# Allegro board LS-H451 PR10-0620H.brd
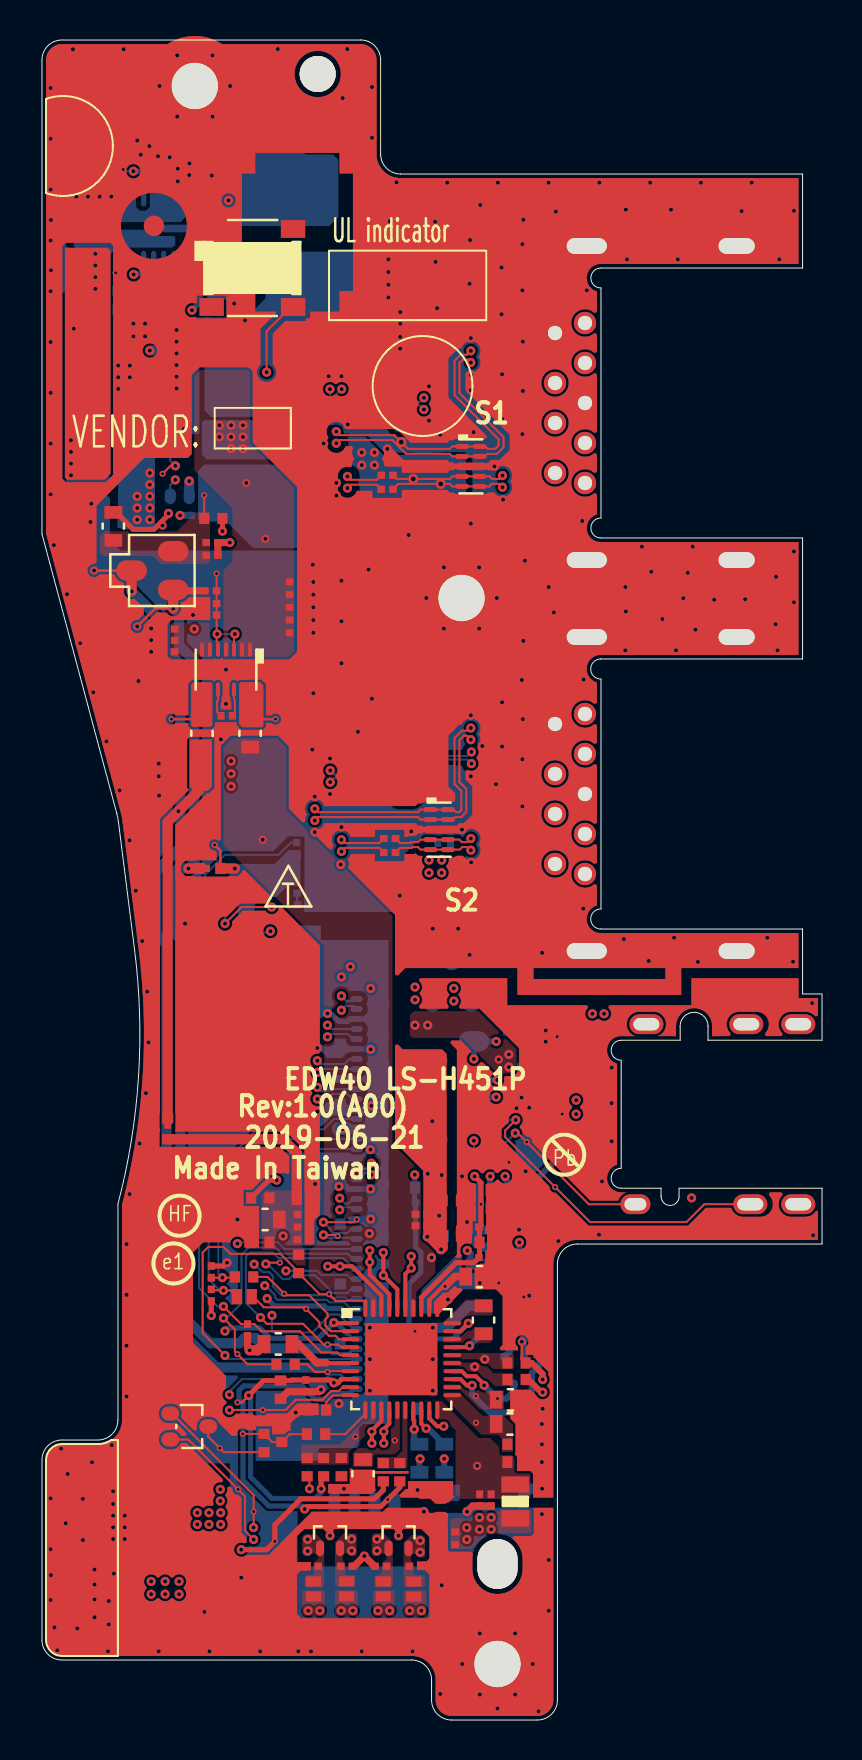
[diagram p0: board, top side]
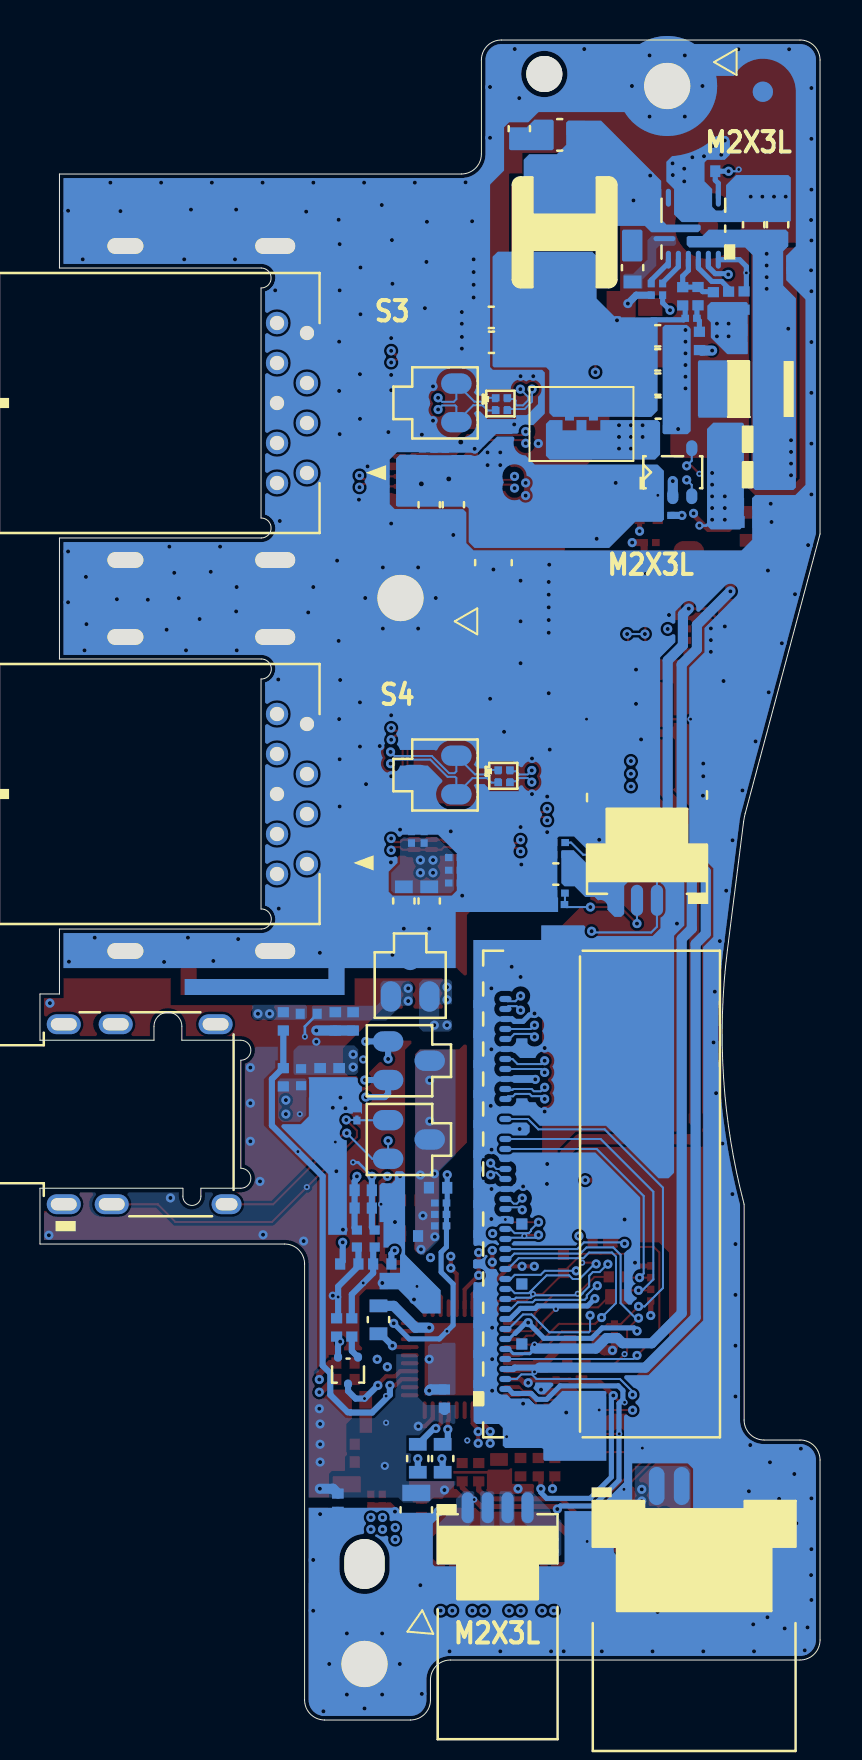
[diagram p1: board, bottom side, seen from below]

Outline 39.05 x 84 mm; copper layers: TOP, GND1, IN1, IN2, GND2, BOTTOM. Coordinates in mm from the lower left corner of the outline.
Outline path: 0,83 arc(0.29,83.71) 1,84 15.95,84 arc(16.66,83.71) 16.95,83 16.95,78.3 arc(17.24,77.59) 17.95,77.3 38.07,77.3 38.07,72.6 27.97,72.6 arc(27.47,72.1) 27.98,71.6 27.98,60.1 arc(27.47,59.61) 27.97,59.1 38.07,59.1 38.07,53.05 27.97,53.05 arc(27.47,52.55) 27.98,52.05 27.98,40.55 arc(27.47,40.06) 27.97,39.55 38.07,39.55 38.07,36.3 39.05,36.3 39.05,33.99 33.34,33.99 33.34,34.69 arc(32.64,35.39) 31.94,34.69 31.94,33.99 28.99,33.99 arc(28.49,33.49) 28.99,32.99 28.99,27.59 arc(28.49,27.09) 28.99,26.59 30.99,26.59 30.99,26.19 arc(31.44,25.74) 31.89,26.19 31.89,26.59 39.05,26.59 39.05,23.8 26.8,23.8 arc(26.09,23.51) 25.8,22.8 25.8,1 arc(25.51,0.29) 24.8,0 20.5,0 arc(19.79,0.29) 19.5,1 19.5,2 arc(19.21,2.71) 18.5,3 1,3 arc(0.29,3.29) 0,4 0,13 arc(0.29,13.71) 1,14 2.8,14 arc(3.51,14.29) 3.8,15 3.8,25.79 arc(4.83,32.1) 4.64,38.5 3.83,44.92 arc(3.79,45.12) 3.75,45.32 0,59.3 0,83

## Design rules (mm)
net group DMIC: nets DMIC_DATA DMIC_DATA_CODEC
net group USB3_CRX_DTX_3: nets USB3_CRX_DTX_N3 USB3_CRX_DTX_P3
net group USB3_CRX_DTX_4: nets USB3_CRX_DTX_N4 USB3_CRX_DTX_P4
net group USB3_CTX_C_DRX_3: nets USB3_CTX_C_DRX_N3 USB3_CTX_C_DRX_P3
net group USB3_CTX_C_DRX_4: nets USB3_CTX_C_DRX_N4 USB3_CTX_C_DRX_P4
net group USB3_CTX_DRX_3: nets USB3_CTX_DRX_N3 USB3_CTX_DRX_P3
net group USB3_CTX_DRX_4: nets USB3_CTX_DRX_N4 USB3_CTX_DRX_P4
net group USB20_1_R: nets USB20_N1_R USB20_P1_R
net group USB20_1_R1: nets USB20_N1_R1 USB20_P1_R1
net group USB20_2_R: nets USB20_N2_R USB20_P2_R
net group USB20_2_R1: nets USB20_N2_R1 USB20_P2_R1
net group 10.6: nets HDA_BIT_CLK_R
net group 15: nets AUD_HP1_JACK_L1 AUD_HP1_JACK_R1 DMIC_CLK DMIC_CLK_CODEC HPOUT_L HPOUT_R LINE1-L_C LINE1-L_R LINE1_L LINE1_R
net group HDA: nets HDA_SDIN0 HDA_SDIN0_R HDA_SDOUT_R HDA_SYNC_R
net group UA7: nets +LINE1_VREFO_L +MIC2-VREFO LDO2_CAP
nets with their own width: min track width 0.254; nets +1.8V_CPVDD +1.8VS_AUDIO +3V_DVDD +3VALW +5V_AVDD +5VS_FAN +RTC_CELL
nets with their own width: min track width 0.305; nets AUD_HP1_JACK_L AUD_HP1_JACK_R CBN CBP CPVEE
nets with their own width: min track width 0.381; nets BST_5VB LDO1_CAP LDO3_CAP MIC_CAP
nets with their own width: min track width 0.508; nets +1.8V_PRIM +3VS_AUDIO +3VS_AUDIO_R +5VS AGND AUD_AGND GND
nets with their own width: min track width 1.016; nets RING2 RING2_R SLEEVE SLEEVE_R SPK_-OUT-L+ SPK_-OUT-L- SPK_-OUT-R+ SPK_-OUT-R- SPK_L+ SPK_L- SPK_R+ SPK_R-
nets with their own width: min track width 2.032; nets +USB3_VCC
nets with their own width: min track width 3.048; nets +5VS_AUDIO +5VS_AUDIO_R
nets with their own width: min track width 3.302; nets +5VALW
nets with their own width: min track width 3.556; nets +5VALWBP
nets with their own width: min track width 4.064; nets B+

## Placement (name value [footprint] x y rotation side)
C27  22U_0603_6.3V6M  [C_0603]  12.51 42.3 0 bottom
C84  100P_0201_25V8J  [C_0201]  12.75 43.26 0 bottom
C123  82P_0201_25V8J  [C_0201]  12.77 41.34 0 bottom
C124  82P_0201_25V8J  [C_0201]  12.75 43.87 0 bottom
CA14  0.1U_0402_16V7K  [C_0402]  13.26 14.29 0 top
CA18  1U_0603_16V7  [C_0603]  22.1 19.31 90 bottom
CA19  10U_0402_10V6M  [C_0402]  23.3 12.9 0 top
CA20  10U_0603_6.3V6M  [C_0603]  24.13 14.8 180 top
CA24  0.1U_0201_10V6K  [C_0201]  21.87 23.12 0 top
CA29  10U_0402_10V6M  [C_0402]  21.9 23.88 0 top
CA32  10U_0603_6.3V6M  [C_0603]  11.12 18.8 0 top
CA33  0.1U_0201_10V6K  [C_0201]  13.21 17 270 top
CA36  680P_0402_50V7K  [C_0402]  25.02 32.59 270 bottom
CA37  680P_0402_50V7K  [C_0402]  24.26 35.39 270 bottom
CA39  10U_0402_6.3V6M  [C_0402]  11.94 16.97 270 top
CA44  1000P_0201_25V7K  [C_0201]  17.25 7.69 180 top
CA45  1000P_0201_25V7K  [C_0201]  18.38 7.69 0 top
CA49  1000P_0201_25V7K  [C_0201]  14.95 7.69 0 top
CA50  1000P_0201_25V7K  [C_0201]  13.82 7.69 180 top
CA51  10U_0603_6.3V6M  [C_0603]  22.61 22.17 180 top
CA81  0.1U_0402_25V6  [C_0402]  21.03 24.2 180 bottom
CA82  0.1U_0402_25V6  [C_0402]  20.97 24.2 180 top
CA83  0.1U_0402_25V6  [C_0402]  24.13 11.32 270 bottom
CA144  3300P_0201_25V7K  [C_0201]  9.53 50.21 270 top
CA145  1000P_0201_25V7K  [C_0201]  8.96 50.21 270 top
CA146  1U_0201_6.3V6M  [C_0201]  6.65 53.98 180 top
CA147  0.1U_0201_10V6K  [C_0201]  7.6 47.19 180 top
CA148  0.1U_0201_10V6K  [C_0201]  18.7 24.71 0 top
CA150  0.1U_0201_10V6K  [C_0201]  12.79 24.64 0 top
CA151  10U_0402_6.3V6M  [C_0402]  11.38 23.88 180 top
CA152  1U_0201_6.3V6M  [C_0201]  12.4 55.63 0 top
CA153  0.1U_0201_10V6K  [C_0201]  8.22 58.87 0 top
CA161  680P_0402_50V7K  [C_0402]  22.43 26.49 180 bottom
CA162  680P_0402_50V7K  [C_0402]  23.3 26.49 0 bottom
CA163  680P_0402_50V7K  [C_0402]  23.37 35.39 270 bottom
CA164  680P_0402_50V7K  [C_0402]  24.07 32.59 270 bottom
CA165  10U_0603_10V6M  [C_0603]  20.13 13.79 270 bottom
CA166  10U_0603_10V6M  [C_0603]  18.89 13.79 270 bottom
CA300  68P_0201_25V8  [C_0201]  19.28 25.28 180 top
CA301  68P_0201_25V8  [C_0201]  7.01 47.82 0 top
CA302  68P_0201_25V8  [C_0201]  6.06 53.41 0 top
CA305  0.1U_0201_10V6K  [C_0201]  6.65 54.55 180 top
CA306  68P_0201_25V8  [C_0201]  12.98 55 180 top
CA307  0.1U_0201_10V6K  [C_0201]  12.4 54.36 0 top
CA309  68P_0201_25V8  [C_0201]  22.46 24.64 180 top
CA313  100P_0201_25V8J  [C_0201]  8.22 58.24 0 top
CA379  68P_0201_50V8J  [C_0201]  12.79 25.28 0 top
CA380  10U_0603_6.3V6M  [C_0603]  16.07 13.02 270 top
CA382  .1U_0402_16V7K  [C_0402]  14.99 13.1 270 top
CA383  10U_0603_6.3V6M  [C_0603]  11.88 25.03 180 top
CA384  10P_0201_50V8J  [C_0201]  12.79 24.01 0 top
CA386  2.2U_0603_6.3V6K  [C_0603]  22.1 20.71 270 top
CA387  68P_0201_50V8J  [C_0201]  18.7 25.85 0 bottom
CA390  10P_0201_50V8J  [C_0201]  21.91 11.28 270 top
CA393  10P_0201_50V8J  [C_0201]  20.68 9.4 180 top
CA394  2.2U_0603_6.3V6K  [C_0603]  22.74 16.01 0 top
CA395  10P_0201_50V8J  [C_0201]  18.7 25.28 0 bottom
CA396  .1U_0402_16V7K  [C_0402]  12.75 26.04 0 top
CA399  68P_0201_50V8J  [C_0201]  22.48 11.28 270 top
CA401  68P_0201_50V8J  [C_0201]  20.68 8.77 180 top
CA429  10U_0402_10V6M  [C_0402]  18.66 26.61 0 bottom
CA430  0.1U_0201_10V6K  [C_0201]  18.7 24.71 0 bottom
CA555  47P_0201_25V8J  [C_0201]  10.29 19.21 90 top
CA568  82P_0201_25V8J  [C_0201]  8.47 22.12 90 top
CA569  82P_0201_25V8J  [C_0201]  8.47 21.53 270 top
CA999  0.1U_0201_10V6K  [C_0201]  8.74 55.25 180 top
CA1000  0.1U_0402_25V6  [C_0402]  20.97 25.98 180 top
CE99  0.01U_0201_16V7  [C_0201]  12.79 40.77 0 bottom
CI140  0.1U_0201_10V6K  [C_0201]  17.11 43.38 0 top
CI141  0.1U_0201_10V6K  [C_0201]  17.11 44.08 0 top
CI142  0.1U_0201_10V6K  [C_0201]  16.98 61.54 0 top
CI143  0.1U_0201_10V6K  [C_0201]  16.98 62.24 0 top
CU3  1U_0201_6.3V6M  [C_0201]  19.9 62.99 90 bottom
CU4  1U_0201_6.3V6M  [C_0201]  20.48 60.92 270 bottom
CU5  22U_0603_6.3V6M  [C_0603]  18.36 61.47 270 bottom
CU6  22U_0603_6.3V6M  [C_0603]  19.56 61.47 270 bottom
CU7  100U_1206_6.3V6M  [C_1206]  16.35 59.19 270 bottom
CU8  100P_0201_25V8J  [C_0201]  18.75 63.56 270 bottom
CU9  0.1U_0201_10V6K  [C_0201]  19.32 62.97 90 bottom
CU10  12P_0201_25V8J  [C_0201]  21.05 60.92 270 bottom
CU13  1U_0201_6.3V6M  [C_0201]  8.26 64.55 180 bottom
CU16  100P_0201_25V8J  [C_0201]  12.98 56.27 180 top
CU17  0.1U_0201_10V6K  [C_0201]  12.4 56.9 0 top
CU18  0.1U_0201_10V6K  [C_0201]  8.04 60.23 180 bottom
CU19  22U_0603_6.3V6M  [C_0603]  19.56 41.66 270 bottom
CU20  22U_0603_6.3V6M  [C_0603]  20.83 41.66 270 bottom
CU21  1U_0201_6.3V6M  [C_0201]  19.82 43.85 90 bottom
CU23  1U_0201_6.3V6M  [C_0201]  20.45 43.85 90 bottom
CU24  100P_0201_25V8J  [C_0201]  18 41.85 0 bottom
CU25  0.1U_0201_10V6K  [C_0201]  18.58 42.49 180 bottom
CU26  12P_0201_25V8J  [C_0201]  18.58 43.12 180 bottom
DA8  CEST523NC5VB 3P C/A SOT-523  [L03ESDL5V0CG3-2_SOT-523-3]  17.85 9.98 0 top
DA9  CEST523NC5VB 3P C/A SOT-523  [L03ESDL5V0CG3-2_SOT-523-3]  14.42 9.98 0 top
DA14  AZ5125-02S.R7G_SOT23-3  [AZ5125-02SPR7G_SOT23-3]  19.54 29.03 90 bottom
DA15  AZ5125-02S.R7G_SOT23-3  [AZ5125-02SPR7G_SOT23-3]  19.54 32.96 90 bottom
DA16  AZ5123-02S.R7G_SOT23-3  [AZ5123-02SPR7G_SOT23-3]  20.51 38.26 0 bottom
DA18  BAT54ATB_SOT-523-3  [BAT54ATB_SOT523-3]  23.63 16.79 180 bottom
DA19  -  [BAT54CW_SOT323-3]  8.32 14.67 270 top
DI1  -  [CEST23LC5VB_SOT23-3]  20.29 65.86 270 bottom
DI2  -  [CEST23LC5VB_SOT23-3]  20.29 47.25 270 bottom
EU1  -  [AZ1045-04F_DFN2510P10E-10-9]  21.03 63.68 270 top
EU8  -  [AZ1045-04F_DFN2510P10E-10-9]  19.44 45.52 270 top
FD1  FIDUCAL  [FIDUCIAL_C40M80]  5.6 74.71 0 top
FD2  FIDUCIAL  [FIDUCIAL_C40M80]  2.86 81.41 180 bottom
H1  HOLEA  [H_2P3-G]  21 56.1 0 top
H2  HOLEA  [H_2P3-G]  22.8 2.8 0 top
H3  HOLEA  [H_1P8N]  13.8 82.3 0 top
H20  HOLEA  [H_2P5X2P0N]  22.8 7.8 90 top
H21  HOLEA  [H_2P3-G]  7.65 81.7 0 top
JFAN1  ACES_50224-00401-001  [ACES_50224-00401-001_4P]  7.16 40.98 0 bottom
JHP1  YUQIU_PJ036-F06M1BE-A  [YUQIU_PJ036-F06M1BE-A_6P-T]  37.85 25.79 90 bottom
JIO1  I-PEX_20849-040E-01  [I-PEX_20849-040E-01_40P-T]  15.75 16.55 90 bottom
JIO2  ACES_50279-0040C-P01  [ACES_50279-0040C-P01_4P]  8.17 11.7 180 bottom
JSPK1  ACES_50224-00401-001  [ACES_50224-00401-001_4P]  17.64 10.62 180 bottom
JUSB1  LOTES_AUSB0014-P003A  [LOTES_AUSB0014-P003A_9P]  25.68 62.35 270 bottom
JUSB2  LOTES_AUSB0014-P003A  [LOTES_AUSB0014-P003A_9P]  25.68 42.8 270 bottom
L7  BLM15PX471SN1D_2P  [MURAT_BLM15PX471SN1D_2P]  9.75 21.16 0 top
LA1  HCB2012KF-600T30  [TAI-T_HCB2012KF-121T50_2P]  23.69 11.78 270 top
LA5  BLM15PX181SN1D_2P  [MURAT_BLM15PX181SN1D_2P]  13.59 6.18 90 top
LA6  BLM15PX181SN1D_2P  [MURAT_BLM15PX181SN1D_2P]  15.24 6.18 90 top
LA7  BLM15PX181SN1D_2P  [MURAT_BLM15PX181SN1D_2P]  17.09 6.18 90 top
LA8  BLM15PX181SN1D_2P  [MURAT_BLM15PX181SN1D_2P]  18.61 6.17 90 top
LA27  BLM15PX330SN1D_2P  [MURAT_BLM15PX330SN1D_2P]  26.02 35.31 180 bottom
LA28  BLM15PD800SN1D_2P  [MURAT_BLM15PD800SN1D_2P]  22.29 23.65 90 bottom
LA29  BLM15PX330SN1D_2P  [MURAT_BLM15PX330SN1D_2P]  25.98 31.71 90 bottom
LA30  BLM15PD800SN1D_2P  [MURAT_BLM15PD800SN1D_2P]  23.18 23.65 90 bottom
LU1  DLM0NSN900HY2D_4P  [MURAT_DLM0NSN900HY2D_4P-NPM]  16.26 66.05 180 bottom
LU2  DLM0NSN900HY2D_4P  [MURAT_DLM0NSN900HY2D_4P-NPM]  16.12 47.44 180 bottom
NOREF  -  []  1.28 63.7 0 top
NOREF#2  -  []  21 56.1 0 top
NOREF#3  -  []  22.8 2.8 0 top
NOREF#4  -  []  -1.33 -39.24 0 top
NOREF#5  -  []  6.32 72.2 0 top
NOREF#6  -  []  11.19 40.68 0 top
NOREF#7  -  []  5.69 32.96 0 top
NOREF#8  -  []  7.65 81.7 0 top
NOREF#9  -  []  22.8 2.8 0 top
NOREF#10  -  []  -72.55 45.68 0 top
PC517  33U_B3_16VM_R45M  [C_B3]  2.69 66.55 0 bottom
PC518  0.1U_0402_25V6  [C_0402]  2.97 69.51 0 bottom
PC519  2200P_0402_50V7K  [C_0402]  2.98 68.61 0 bottom
PC520  10U_0603_25V6M  [C_0603]  2.12 74.05 90 bottom
PC521  10U_0603_25V6M  [C_0603]  3.32 74.05 90 bottom
PC522  22U_0603_6.3V6M  [C_0603]  8.83 69.21 180 bottom
PC523  22U_0603_6.3V6M  [C_0603]  8.83 68.01 180 bottom
PC524  22U_0603_6.3V6M  [C_0603]  8.83 66.79 180 bottom
PC525  22U_0603_6.3V6M  [C_0603]  15.74 70.13 0 bottom
PC526  22U_0603_6.3V6M  [C_0603]  15.74 68.89 0 bottom
PC527  22U_0603_6.3V6M  [C_0603]  8.82 65.6 180 bottom
PC528  2.2U_0402_6.3V6M  [C_0402]  5.24 77.44 0 bottom
PC529  0.22U_0402_16V7K  [C_0402]  9.31 74.24 90 bottom
PC530  220P_0201_25V7K  [C_0201]  6.16 70.08 0 bottom
PC531  680P_0603_50V7K  [C_0603]  15.05 78.86 90 bottom
PC535  1000P_0402_25V8J  [C_0402]  4.05 60.81 180 bottom
PC536  1U_0402_25V6K  [C_0402]  4.02 59.9 180 bottom
PC541  100P_0201_25V8J  [C_0201]  16.16 72.4 0 bottom
PC542  100P_0201_25V8J  [C_0201]  16.16 71.76 0 bottom
PC543  2200P_0201_16V7K  [C_0201]  16.16 71.13 0 bottom
PC544  0.1U_0201_6.3V6K  [C_0201]  16.16 73.03 0 bottom
PC545  100P_0201_25V8J  [C_0201]  2.07 73.06 180 bottom
PC546  100P_0201_25V8J  [C_0201]  2.07 72.48 180 bottom
PJP502  PAD-OPEN 4x4m  [JUMP_43X118]  11.94 65.35 270 bottom
PL502  1.5UH_MMD-05AHN1R5M-M1L_6.2A_20%  [MAG_MMD-05AHN1R5M-M1L_2P]  12.78 76.56 270 bottom
PL513  -  [5A_Z80_0805_2P]  4.47 62.26 180 bottom
PL514  -  [5A_Z80_0805_2P]  4.47 64.04 180 bottom
PR511  150K_0201_5%  [R_0201]  7.88 71.82 270 bottom
PR512  0_0402_5%  [R_0402]  3.8 70.52 90 bottom
PR513  0_0201_5%  [R_0201]  8.45 71.24 90 bottom
PR514  0_0603_5%  [R_0603]  9.38 71.91 90 bottom
PR515  0_0402_5%  [R_0402]  4.58 71.42 270 bottom
PR516  274K_0402_1%  [R_0402]  6.04 68.5 90 bottom
PR517  499_0402_1%  [R_0402]  6.11 70.74 90 bottom
PR518  19.1K_0402_1%  [R_0402]  6.87 70.73 90 bottom
PR519  10K_0402_1%  [R_0402]  5.34 71.39 270 bottom
PR520  4.7_0805_5%  [R_0805]  12.18 79.26 0 bottom
PU502  -  [NB502GQ-Z_QFN16_3X3]  5.49 74.07 0 bottom
QA1  -  [LN2306LT1G_SOT23-3]  4.49 57.47 270 top
RA9  1K_0402_5%  [R_0402]  11.12 13.39 90 top
RA10  100K_0402_5%  [R_0402]  24.21 13.79 180 top
RA17  33_0402_5%  [R_0402]  11.74 17.79 0 top
RA22  0_0402_5%  [R_0402]  19.94 11.07 270 top
RA23  0_0402_5%  [R_0402]  18.8 15.61 90 bottom
RA25  0_0805_5%  [R_0805]  20.21 11.36 270 bottom
RA29  0_0402_5%  [R0402_0OHM]  6.29 29.95 270 top
RA32  1K_0402_5%  [R_0402]  24.21 17.85 180 top
RA33  4.7K_0402_5%  [R_0402]  24.2 19.17 90 bottom
RA36  0_0402_5%  [R_0402]  10.47 26.1 0 top
RA112  0.01_0603_1%  [R_0603]  3.57 58.98 90 top
RA115  0.01_0603_1%  [R_0603]  8 50.04 270 top
RA116  0.01_0603_1%  [R_0603]  10.42 50.04 270 top
RA122  10K_0201_5%  [R_0201]  8.16 56.46 0 top
RA133  10_0402_1%  [R_0402]  21.45 22.8 0 bottom
RA134  10_0402_1%  [R_0402]  24.02 22.8 180 bottom
RA168  0_0201_5%  [R0201_0OHM]  23.18 30 90 bottom
RA169  2.2K_0402_5%  [R_0402]  26.86 34.47 90 bottom
RA170  10K_0402_5%  [R_0402]  22.43 25.6 180 bottom
RA171  10K_0402_5%  [R_0402]  23.3 25.6 0 bottom
RA172  2.2K_0402_5%  [R_0402]  26.86 32.59 270 bottom
RA200  4.7K_0402_5%  [R_0402]  23.44 19.17 90 bottom
RA202  1K_0402_5%  [R_0402]  24.21 17.02 180 top
RA206  100K_0402_5%  [R_0402]  12.84 23.26 270 top
RA207  200K_0402_1%  [R_0402]  13.28 12.19 90 top
RA209  0_0402_5%  [R_0402]  13.31 15.5 0 top
RA213  0_0402_5%  [R_0402]  17.09 12.85 270 top
RA217  100K_0402_5%  [R_0402]  14.1 13.1 270 top
RA222  33_0402_5%  [R_0402]  9.66 22.15 0 top
RA225  0_0402_5%  [R_0402]  8.12 60.08 0 top
RA227  0_0402_5%  [R_0402]  17.91 12.85 270 top
RA511  20K_0201_5%  [R_0201]  8.74 55.82 180 top
RF10  0_0402_5%  [R0402_0OHM]  8.02 42.58 0 top
RU1  0_0201_5%  [R_0201]  15.65 65.47 0 bottom
RU2  0_0201_5%  [R_0201]  15.65 66.11 0 bottom
RU3  0_0201_5%  [R_0201]  15.52 47.5 0 bottom
RU4  0_0201_5%  [R_0201]  15.52 46.87 0 bottom
RV30  10K_0402_5%  [R_0402]  12.01 13.9 90 top
SW3  SKRBACE010_4P  [SW_SKRBACE010_4P]  8.49 74.55 0 top
UA2  AOZ1331DI_DFN_14  [EM5209VF_DFN14_3X2]  10.41 53.52 180 top
UA7  -  [ALC3204-CG_MQFN40_5X5]  15.44 19.84 0 top
UU1  -  [SY6288D20AAC_SOT23-5]  8.32 61.19 180 bottom

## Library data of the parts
C27 CA18 CA20 CA32 CA51 CA165 CA166 CA380 CA383 CA386 CA394 CU5 CU6 CU19 CU20 PC520-PC527 PC531 = C_0603
C84 C123 C124 CA24 CA33 CA44 CA45 CA49 CA50 CA144-CA148 CA150 CA152 CA153 CA300-CA302 CA305-CA307 CA309 CA313 CA379 CA384 CA387 CA390 CA393 CA395 CA399 CA401 CA430 CA555 CA568 CA569 CA999 CE99 CI140-CI143 CU3 CU4 CU8-CU10 CU13 CU16-CU18 CU21 CU23-CU26 PC530 PC541-PC546 = C_0201
CA14 CA19 CA29 CA36 CA37 CA39 CA81-CA83 CA151 CA161-CA164 CA382 CA396 CA429 CA1000 PC518 PC519 PC528 PC529 PC535 PC536 = C_0402
CU7 = C_1206
DA8 DA9 = L03ESDL5V0CG3-2_SOT-523-3
DA14 DA15 = AZ5125-02SPR7G_SOT23-3
DA16 = AZ5123-02SPR7G_SOT23-3
DA18 = BAT54ATB_SOT523-3
DA19 = BAT54CW_SOT323-3
DI1 DI2 = CEST23LC5VB_SOT23-3
EU1 EU8 = AZ1045-04F_DFN2510P10E-10-9
FD1 FD2 = FIDUCIAL_C40M80
H1 H2 H21 = H_2P3-G
H3 = H_1P8N
H20 = H_2P5X2P0N
JFAN1 JSPK1 = ACES_50224-00401-001_4P
JHP1 = YUQIU_PJ036-F06M1BE-A_6P-T
JIO1 = I-PEX_20849-040E-01_40P-T
JIO2 = ACES_50279-0040C-P01_4P
JUSB1 JUSB2 = LOTES_AUSB0014-P003A_9P
L7 = MURAT_BLM15PX471SN1D_2P
LA1 = TAI-T_HCB2012KF-121T50_2P
LA5-LA8 = MURAT_BLM15PX181SN1D_2P
LA27 LA29 = MURAT_BLM15PX330SN1D_2P
LA28 LA30 = MURAT_BLM15PD800SN1D_2P
LU1 LU2 = MURAT_DLM0NSN900HY2D_4P-NPM
PC517 = C_B3
PJP502 = JUMP_43X118
PL502 = MAG_MMD-05AHN1R5M-M1L_2P
PL513 PL514 = 5A_Z80_0805_2P
PR511 PR513 RA122 RA511 RU1-RU4 = R_0201
PR512 PR515-PR519 RA9 RA10 RA17 RA22 RA23 RA32 RA33 RA36 RA133 RA134 RA169-RA172 RA200 RA202 RA206 RA207 RA209 RA213 RA217 RA222 RA225 RA227 RV30 = R_0402
PR514 RA112 RA115 RA116 = R_0603
PR520 RA25 = R_0805
PU502 = NB502GQ-Z_QFN16_3X3
QA1 = LN2306LT1G_SOT23-3
RA29 RF10 = R0402_0OHM
RA168 = R0201_0OHM
SW3 = SW_SKRBACE010_4P
UA2 = EM5209VF_DFN14_3X2
UA7 = ALC3204-CG_MQFN40_5X5
UU1 = SY6288D20AAC_SOT23-5

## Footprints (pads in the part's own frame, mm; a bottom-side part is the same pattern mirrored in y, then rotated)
5A_Z80_0805_2P
  rect 0.813x1.397 smd: 1(0,0) 2(1.702,0)
ACES_50224-00401-001_4P
  oval 0.61x1.549 smd: 1(0,0) 2(1,0) 3(2,0) 4(3,0)
  rect 1.194x1.803 smd: 5(4.3,-3.875) 6(-1.3,-3.875)
ACES_50279-0040C-P01_4P
  oval 0.787x1.905 smd: 1(0,0) 2(1.25,0) 3(2.5,0) 4(3.75,0)
  rect 1.295x3.353 smd: 5(-2.85,-4.925) 6(6.6,-4.925)
ALC3204-CG_MQFN40_5X5
  oval 0.889x0.203 smd: 1(0,0) 2(0,-0.4) 3(0,-0.8) 4(0,-1.2) 5(0,-1.6) 6(0,-2) 7(0,-2.4) 8(0,-2.8) 9(0,-3.2) 10(0,-3.6) 21(5.1,-3.6) 22(5.1,-3.2) 23(5.1,-2.8) 24(5.1,-2.4) 25(5.1,-2) 26(5.1,-1.6) 27(5.1,-1.2) 28(5.1,-0.8) 29(5.1,-0.4) 30(5.1,0)
  oval 0.203x0.889 smd: 11(0.75,-4.35) 12(1.15,-4.35) 13(1.55,-4.35) 14(1.95,-4.35) 15(2.35,-4.35) 16(2.75,-4.35) 17(3.15,-4.35) 18(3.55,-4.35) 19(3.95,-4.35) 20(4.35,-4.35) 31(4.35,0.75) 32(3.95,0.75) 33(3.55,0.75) 34(3.15,0.75) 35(2.75,0.75) 36(2.35,0.75) 37(1.95,0.75) 38(1.55,0.75) 39(1.15,0.75) 40(0.75,0.75)
  rect 3.607x3.607 smd: 41(2.55,-1.8)
AZ1045-04F_DFN2510P10E-10-9
  oval 0.254x0.686 smd: 1(0,0) 2(0.5,0) 4(1.5,0) 5(2,0) 6(2,0.875) 7(1.5,0.875) 8(0.5,0.875) 9(0,0.875)
  oval 0.381x1.549 smd: 3(1,0.437)
AZ5123-02SPR7G_SOT23-3
  oval 1.016x1.524 smd: 1(0,0) 2(0.965,2.083) 3(-0.965,2.083)
AZ5125-02SPR7G_SOT23-3
  oval 1.016x1.524 smd: 1(0,0) 2(0.965,2.083) 3(-0.965,2.083)
BAT54ATB_SOT523-3
  oval 0.406x0.457 smd: 1(0,0) 2(0.5,1.35) 3(-0.5,1.35)
BAT54CW_SOT323-3
  oval 0.711x0.889 smd: 1(0,0) 2(-0.65,-1.9) 3(0.65,-1.9)
C_0201
  rect 0.381x0.356 smd: 1(0,0) 2(0.584,0)
C_0402
  rect 0.508x0.584 smd: 1(0,0) 2(0.914,0)
C_0603
  rect 0.635x0.889 smd: 1(0,0) 2(1.397,0)
C_1206
  rect 1.016x1.778 smd: 1(0,0) 2(2.667,0)
C_B3
  rect 1.346x2.692 smd: 1(0,0) 2(2.75,0)
CEST23LC5VB_SOT23-3
  oval 1.016x1.524 smd: 1(0,0) 2(0.965,2.083) 3(-0.965,2.083)
EM5209VF_DFN14_3X2
  oval 0.203x0.711 smd: 1(0,0) 2(0.4,0) 3(0.8,0) 4(1.2,0) 5(1.6,0) 6(2,0) 7(2.4,0) 8(2.4,2) 9(2,2) 10(1.6,2) 11(1.2,2) 12(0.8,2) 13(0.4,2) 14(0,2)
  rect 2.591x0.991 smd: 15(1.2,1)
FIDUCIAL_C40M80
  round 1.016 smd: 1(0,0)
H_1P8N
  round 1.803 hole 1.803 unplated: (0,0)
H_2P3-G
  round 2.819 hole 2.311: 1(0,0)
H_2P5X2P0N
  oval 2.489x2.007 hole 2.489x2.007 unplated: (0,0)
I-PEX_20849-040E-01_40P-T
  oval 0.305x0.61 smd: 1(0,0) 2(0.5,0) 3(1,0) 4(1.5,0) 5(2,0) 6(2.5,0) 7(3,0) 8(3.5,0) 9(4,0) 10(4.5,0) 11(5,0) 12(5.5,0) 13(6,0) 14(6.5,0) 15(7,0) 16(7.5,0) 17(8,0) 18(8.5,0) 19(9,0) 20(9.5,0) 21(10,0) 22(10.5,0) 23(11,0) 24(11.5,0) 25(12,0) 26(12.5,0) 27(13,0) 28(13.5,0) 29(14,0) 30(14.5,0) 31(15,0) 32(15.5,0) 33(16,0) 34(16.5,0) 35(17,0) 36(17.5,0) 37(18,0) 38(18.5,0) 39(19,0) 40(19.5,0)
  rect 0.559x0.711 smd: 41(-0.9,-0.05) 42(20.4,-0.05)
  rect 1.194x1.702 smd: 43(-2.93,-2.8) 44(22.43,-2.8)
  rect 0.406x0.559 smd: 45(-1.25,1.24) 46(0.25,1.325) 47(1.75,1.325) 48(3.25,1.325) 49(4.75,1.325) 50(6.25,1.325) 51(7.75,1.325) 52(9.25,1.325) 53(10.25,1.325) 54(11.75,1.325) 55(13.25,1.325) 56(14.75,1.325) 57(16.25,1.325) 58(17.75,1.325) 59(19.25,1.325) 60(20.75,1.24)
  rect 0.61x1.194 smd: 61(-2.645,-0.7) 62(22.145,-0.7)
  rect 0.559x0.559 smd: 63(2.25,-0.825) 64(5.25,-0.825) 65(8.25,-0.825) 66(11.25,-0.825) 67(14.25,-0.825) 68(17.25,-0.825)
JUMP_43X118
  custom 0.187x0.187 smd: 1(0,0) 2(1.1,0)
L03ESDL5V0CG3-2_SOT-523-3
  oval 0.406x0.787 smd: 1(0,0) 2(-0.5,-1.4) 3(0.5,-1.4)
LN2306LT1G_SOT23-3
  oval 1.016x1.524 smd: 1(0,0) 2(0.965,2.083) 3(-0.965,2.083)
LOTES_AUSB0014-P003A_9P
  round 1.118 hole 0.711: 1(0,0) 2(-2.5,0) 3(-4.5,0) 4(-7,0) 5(-7.5,-1.5) 6(-5.5,-1.5) 7(-3.5,-1.5) 8(-1.5,-1.5) 9(0.5,-1.5)
  oval 1.549x2.769 hole 0.787x2.007: 10(-11.35,-1.59) 11(4.35,-1.59)
  oval 1.549x2.565 hole 0.787x1.803: 12(-11.35,-9.09) 13(4.35,-9.09)
MAG_MMD-05AHN1R5M-M1L_2P
  rect 2.159x2.794 smd: 1(0,0) 2(4.35,0)
MURAT_BLM15PD800SN1D_2P
  rect 0.457x0.508 smd: 1(0,0) 2(0.85,0)
MURAT_BLM15PX181SN1D_2P
  rect 0.508x0.762 smd: 1(0,0) 2(0.75,0)
MURAT_BLM15PX330SN1D_2P
  rect 0.457x0.508 smd: 1(0,0) 2(0.85,0)
MURAT_BLM15PX471SN1D_2P
  rect 0.508x0.762 smd: 1(0,0) 2(0.75,0)
MURAT_DLM0NSN900HY2D_4P-NPM
  rect 0.305x0.305 smd: 1(0,0) 2(0.6,0) 3(0.6,-0.5) 4(0,-0.5)
NB502GQ-Z_QFN16_3X3
  oval 2.311x0.254 smd: 1(0,0) 2(0,-1) 9(1.7,-0.5)
  oval 0.254x0.889 smd: 3(-0.4,-2.05) 4(0.1,-2.05) 5(0.6,-2.05) 6(1.1,-2.05) 7(1.6,-2.05) 8(2.1,-2.05) 11(2.1,1.05) 12(1.6,1.05) 13(1.1,1.05) 14(0.6,1.05) 15(0.1,1.05) 16(-0.4,1.05)
  oval 1.092x0.254 smd: 10(2.3,0)
R0201_0OHM
  custom 0.089x0.089 smd: 1(0,0)
  rect 0.381x0.356 smd: 2(0.584,0)
R0402_0OHM
  custom 0.14x0.14 smd: 1(0,0)
  rect 0.508x0.559 smd: 2(0.914,0)
R_0201
  rect 0.381x0.356 smd: 1(0,0) 2(0.584,0)
R_0402
  rect 0.508x0.559 smd: 1(0,0) 2(0.914,0)
R_0603
  rect 0.635x0.889 smd: 1(0,0) 2(1.397,0)
R_0805
  rect 0.813x1.397 smd: 1(0,0) 2(1.702,0)
SW_SKRBACE010_4P
  rect 1.219x0.889 smd: 1(0,0) 2(4.075,0) 3(0,-3.9) 4(4.075,-3.9)
SY6288D20AAC_SOT23-5
  oval 0.559x0.787 smd: 1(0,0) 2(0.95,0) 3(1.9,0) 4(1.9,2.4) 5(0,2.4)
TAI-T_HCB2012KF-121T50_2P
  rect 0.813x1.397 smd: 1(0,0) 2(1.702,0)
YUQIU_PJ036-F06M1BE-A_6P-T
  oval 0.991x1.702 hole 0.61x1.295: 1(0,0) 2(9,-7.6) 3(9,-2.6) 4(9,0) 6(0,-2.4)
  oval 0.991x1.499 hole 0.61x1.092: 5(0,-8.15)

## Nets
+1.8V_CPVDD: CA387.1 CA395.1 CA429.1 CA430.1 RA225.2 UA7.29
+1.8V_PRIM: JIO1.3 QA1.1
+1.8VS_AUDIO: CA24.1 CA29.1 CA309.2 RA36.1 RA112.2 UA7.33
+3V_DVDD: CA33.1 CA39.1 CA150.1 CA151.1 CA379.1 CA383.1 CA384.1 CA396.1 JIO1.6 RA29.2 RA36.2 RA206.1 RA217.2 UA7.1 UA7.8
+3VALW: CA146.1 CA302.2 CA305.1 JIO1.8 RA213.2 UA2.6 UA2.7
+3VS_AUDIO: CA147.1 CA301.2 RA29.1 RA115.2
+3VS_AUDIO_R: RA115.1 UA2.8 UA2.9
+5V_AVDD: CA19.1 CA390.1 CA399.1 LA1.1 UA7.20
+5VALW: CA152.1 CA306.2 CA307.1 CU13.1 CU16.2 CU17.1 PJP502.2 UA2.1 UA2.2 UA2.4 UU1.5
+5VALWBP: PC522.1 PC523.1 PC524.1 PC525.1 PC526.1 PC527.1 PC530.2 PC541.1 PC542.1 PC543.1 PC544.1 PJP502.1 PL502.2 PR518.1
+5VS: JIO1.5 QA1.2 RA122.1 RF10.1
+5VS_AUDIO: CA148.1 CA300.2 CA393.1 CA401.1 LA1.2 RA116.2 UA7.34 UA7.39
+5VS_AUDIO_R: RA116.1 UA2.13 UA2.14
+5VS_FAN: C27.1 C84.1 JFAN1.4 RF10.2
AGND: CA19.2 CA20.1 CA24.2 CA29.2 CA36.2 CA37.2 CA51.1 CA81.1 CA82.1 CA83.1 CA161.2 CA162.2 CA163.2 CA164.2 CA309.1 CA380.2 CA394.2 CA1000.1 RA10.1 RA22.1 RA23.1 RA25.1 RA168.2 RA170.2 RA171.2 UA7.19 UA7.31
GND: C27.2 C84.2 C123.2 C124.2 CA18.2 CA32.1 CA33.2 CA39.2 CA44.2 CA45.2 CA49.2 CA50.2 CA81.2 CA82.2 CA83.2 CA144.2 CA145.2 CA146.2 CA147.2 CA148.2 CA150.2 CA151.2 CA152.2 CA153.2 CA300.1 CA301.1 CA302.1 CA305.2 CA306.1 CA307.2 CA313.2 CA379.2 CA383.2 CA384.2 CA387.2 CA390.2 CA393.2 CA395.2 CA396.2 CA399.2 CA401.2 CA429.2 CA430.2 CA555.1 CA568.2 CA569.2 CA999.2 CA1000.2 CE99.2 CU3.2 CU4.2 CU5.2 CU6.2 CU7.2 CU8.1 CU9.2 CU10.2 CU13.2 CU16.1 CU17.2 CU18.2 CU19.2 CU20.2 CU21.2 CU23.2 CU24.1 CU25.2 CU26.2 DA8.1 DA9.1 DA14.1 DA15.1 DA16.1 DI1.1 DI2.1 EU1.3 EU8.3 H1.1(TP-1) H2.1(TP-1) H21.1(TP-1) JFAN1.1 JFAN1.5 JFAN1.6 JIO1.18 JIO1.21 JIO1.24 JIO1.27 JIO1.29 JIO1.32 JIO1.35 JIO1.38 JIO1.41 JIO1.42 JIO1.43 JIO1.44 JIO1.45 JIO1.46 JIO1.47 JIO1.48 JIO1.49 JIO1.50 JIO1.51 JIO1.52 JIO1.53 JIO1.54 JIO1.55 JIO1.56 JIO1.57 JIO1.58 JIO1.59 JIO1.60 JIO1.61 JIO1.62 JIO1.66 JIO1.67 JIO1.68 JIO2.3 JIO2.4 JIO2.5 JIO2.6 JSPK1.5 JSPK1.6 JUSB1.4 JUSB1.7 JUSB1.10 JUSB1.11 JUSB1.12 JUSB1.13 JUSB2.4 JUSB2.7 JUSB2.10 JUSB2.11 JUSB2.12 JUSB2.13 PC517.2 PC518.2 PC519.2 PC520.2 PC521.2 PC522.2 PC523.2 PC524.2 PC525.2 PC526.2 PC527.2 PC528.2 PC531.2 PC535.2 PC536.2 PC541.2 PC542.2 PC543.2 PC544.2 PC545.2 PC546.2 PR512.1 PR513.1 PR515.2 PR519.2 PU502.2 PU502.4 PU502.5 PU502.6 PU502.7 RA22.2 RA23.2 RA25.2 RA209.1 RA511.2 RV30.2 SW3.1 UA2.11 UA2.15 UA7.41 UU1.2
V3D3_STB: RA213.1 RA227.1 UA7.16
+LINE1_VREFO_L: DA18.1 UA7.24
+MIC2-VREFO: RA169.1 RA172.1 UA7.23
+RTC_CELL: JIO1.1 RA227.2
+USB3_VCC: CU3.1 CU4.1 CU5.1 CU6.1 CU7.1 CU8.2 CU9.1 CU10.1 CU18.1 CU19.1 CU20.1 CU21.1 CU23.1 CU24.2 CU25.1 CU26.1 JUSB1.1 JUSB2.1 UU1.1
AUD_AGND: CA382.2
AUD_HP1_JACK_L: RA133.1 RA202.2 UA7.25
AUD_HP1_JACK_L1: LA28.1 RA133.2 RA200.2
AUD_HP1_JACK_R: RA32.2 RA134.1 UA7.26
AUD_HP1_JACK_R1: LA30.1 RA33.2 RA134.2
AUD_PC_BEEP: CA14.2 UA7.11
AUD_PC_BEEP_C: DA19.1 RA9.1
AUD_SENSE_A: CA382.1 RA207.2 RA217.1 UA7.12
AUD_VREF: CA394.1 UA7.22
B+: JIO2.1 JIO2.2 PC535.1 PC536.1 PL513.1 PL514.1
BEEP: DA19.3 JIO1.2
BST_5VB: PR514.1 PU502.10
CBN: CA386.2 UA7.28
CBP: CA386.1 UA7.30
CPVEE: CA18.1 UA7.27
DMIC_CLK: L7.2 UA7.3
DMIC_CLK_CODEC: CA569.1 JIO1.26 L7.1
DMIC_DATA: RA222.2 UA7.2
DMIC_DATA_CODEC: CA568.1 JIO1.25 RA222.1
EC_MUTE#: JIO1.4 RA206.2 UA7.40
EN_5V: JIO1.12 PU502.15
FB_5VB: PR517.2 PR518.2 PR519.1 PU502.13
HDA_BIT_CLK_R: CA555.2 JIO1.28 UA7.5
HDA_SDIN0: JIO1.14 RA17.1
HDA_SDIN0_R: RA17.2 UA7.7
HDA_SDOUT_R: JIO1.13 UA7.4
HDA_SYNC_R: JIO1.15 UA7.9
HPOUT_L: CA161.1 DA15.2 JHP1.2 LA28.2 RA170.1
HPOUT_R: CA162.1 DA15.3 JHP1.3 LA30.2 RA171.1
JACK_PLUG: DA14.3 JHP1.5 RA207.1
JACK_PLUG_DET: DA14.2 JHP1.6 RA168.1
LDO1_CAP: CA20.2 RA10.2 UA7.21
LDO2_CAP: CA51.2 UA7.32
LDO3_CAP: CA32.2 UA7.6
LINE1-L_C: CA165.2 RA202.1
LINE1-L_R: CA166.2 RA32.1
LINE1_L: CA165.1 UA7.18
LINE1_R: CA166.1 UA7.17
LX_5VB: PC529.2 PL502.1 PR516.1 PR520.1 PU502.9
MIC_CAP: CA380.1 UA7.15
POK: PR511.1 PU502.12
POWER_SW#_MB: JIO1.7 SW3.4
PWM_FAN1: C124.1 JFAN1.2 JIO1.16
RING2: LA27.1 RA169.2 UA7.13
RING2_R: CA37.1 CA163.1 DA16.2 JHP1.4 LA27.2
SLEEVE: LA29.1 RA172.2 UA7.14
SLEEVE_R: CA36.1 CA164.1 DA16.3 JHP1.1 LA29.2
SPK_-OUT-L+: LA8.1 UA7.35
SPK_-OUT-L-: LA7.1 UA7.36
SPK_-OUT-R+: LA6.1 UA7.38
SPK_-OUT-R-: LA5.1 UA7.37
SPK_L+: CA45.1 DA8.3 JSPK1.1 LA8.2
SPK_L-: CA44.1 DA8.2 JSPK1.2 LA7.2
SPK_R+: CA49.1 DA9.3 JSPK1.3 LA6.2
SPK_R-: CA50.1 DA9.2 JSPK1.4 LA5.2
SPKR: DA19.2 JIO1.9
TACH_FAN1: C123.1 CE99.1 JFAN1.3 JIO1.17
USB3_CRX_DTX_N3: EU1.1 EU1.9 JIO1.31 JUSB1.5
USB3_CRX_DTX_N4: EU8.1 EU8.9 JIO1.37 JUSB2.5
USB3_CRX_DTX_P3: EU1.2 EU1.8 JIO1.30 JUSB1.6
USB3_CRX_DTX_P4: EU8.2 EU8.8 JIO1.36 JUSB2.6
USB3_CTX_C_DRX_N3: CI143.2 EU1.4 EU1.7 JUSB1.8
USB3_CTX_C_DRX_N4: CI141.2 EU8.4 EU8.7 JUSB2.8
USB3_CTX_C_DRX_P3: CI142.2 EU1.5 EU1.6 JUSB1.9
USB3_CTX_C_DRX_P4: CI140.2 EU8.5 EU8.6 JUSB2.9
USB3_CTX_DRX_N3: CI143.1 JIO1.34
USB3_CTX_DRX_N4: CI141.1 JIO1.40
USB3_CTX_DRX_P3: CI142.1 JIO1.33
USB3_CTX_DRX_P4: CI140.1 JIO1.39
USB20_N1_R: JIO1.19 LU1.3 RU1.1
USB20_N1_R1: DI1.2 JUSB1.2 LU1.4 RU1.2
USB20_N2_R: JIO1.22 LU2.3 RU4.1
USB20_N2_R1: DI2.2 JUSB2.2 LU2.4 RU4.2
USB20_P1_R: JIO1.20 LU1.2 RU2.1
USB20_P1_R1: DI1.3 JUSB1.3 LU1.1 RU2.2
USB20_P2_R: JIO1.23 LU2.2 RU3.1
USB20_P2_R1: DI2.3 JUSB2.3 LU2.1 RU3.2
USB_EN#: JIO1.10 UU1.4
USB_OC0#: JIO1.11 UU1.3
N70870692: DA18.2 RA200.1
N70870708: DA18.3 RA33.1
N70876967: CA14.1 RA9.2 RV30.1
N70877136: RA209.2 UA7.10
N70877951: CA153.1 CA313.1 QA1.3 RA112.1 RA225.1
N70878061: CA999.1 RA122.2 RA511.1 UA2.3 UA2.5
N70878070: CA144.1 UA2.12
N70878091: CA145.1 UA2.10
N71020818: PC517.1 PC518.1 PC519.1 PC520.1 PC521.1 PC545.1 PC546.1 PL513.2 PL514.2 PU502.1
N71020841: PR513.2 PU502.11
N71020848: PC529.1 PR514.2
N71020850: PR512.2 PU502.16
N71020923: PC530.1 PR516.2 PR517.1
N71020937: PR515.1 PU502.14
N71020947: PC528.1 PR511.2 PU502.3
N71020994: PC531.1 PR520.2

Pads without a net: FD1 1; FD2 1; JIO1 63 64 65; PU502 8; SW3 2 3

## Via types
v1: diameter 0.457, hole 0.203, TOP to BOTTOM, 547 vias
v2: diameter 0.305, hole 0.152, TOP to BOTTOM, 41 vias
v3: diameter 0.406, hole 0.203, TOP to BOTTOM, 19 vias
v4: diameter 0.508, hole 0.254, TOP to BOTTOM, 3 vias

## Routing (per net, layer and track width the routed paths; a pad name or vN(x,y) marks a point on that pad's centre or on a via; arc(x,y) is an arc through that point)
+1.8V_CPVDD: length 52
  TOP w0.203: UA7.29 20.95,19.44 v1(21.34,19.83)
  TOP w0.254: RA225.2 v1(9.03,59.44)
  IN2 w0.254: v1(18.66,27.26) 16.97,28.95 16.97,37.08 15.24,38.8 15.24,42.38 15.5,42.64 15.5,47.82 14.13,49.19 14.13,58.69 13.37,59.44 v1(9.03,59.44)
  BOTTOM w0.254: v1(21.34,19.83) 20.56,19.06 19.05,19.06 v2(18.67,19.44) 18.37,19.74 18.37,21.8 18.96,22.4 18.96,23.38 18.7,23.65 CA430.1 CA395.1 CA387.1 18.66,25.89 CA429.1 v1(18.66,27.26)
+1.8V_PRIM: length 51.5
  TOP w0.127: QA1.1 v3(2.61,57.47)
  TOP w0.508: v1(4.49,56.43) QA1.1
  BOTTOM w0.305: 14.04,17.62 15.28,17.62 15.35,17.55 JIO1.3
  BOTTOM w0.508: v1(4.49,56.43) 6.16,54.76 6.16,53.54 6.93,52.77 6.93,43.63 5.72,42.42 5.72,39.31 6.23,38.8 6.23,20.14 8.74,17.62 14.04,17.62
+1.8VS_AUDIO: length 94.6
  TOP w0.203: UA7.33 18.99,21.12
  TOP w0.254: 18.99,21.12 20.73,22.87 21.62,22.87 CA24.1 21.9,23.15 CA29.1 21.9,24.62 CA309.2 21.97,24.75 v2(21.97,25.79) 21.97,26.87 v1(21.66,27.18) ; RA36.1 11.36,26.99 11.75,26.99 v1(11.75,26.99) ; v1(6.33,60.33) 6.33,60.26 5.6,59.53 4.57,59.53 3.72,60.38 RA112.2
  IN2 w0.254: v1(21.66,27.18) 21.66,27.37 20.83,28.2 18.36,28.2 17.53,29.03 17.53,39 16.2,40.33 16.2,43.88 15.94,44.14 15.94,47.92 14.51,49.35 14.51,58.85 13.4,59.95 8.78,59.95 7.94,60.79 6.79,60.79 v1(6.33,60.33) 6.33,58.32 11.12,53.54 11.12,41.45 10.93,41.26 10.93,39 11.12,38.8 11.12,36.84 11.75,36.2 v1(11.75,26.99)
+3V_DVDD: length 42.4
  TOP w0.127: v1(10.35,16.22) 10.01,15.88 v2(9.78,15.88)
  TOP w0.203: UA7.1 14.64,19.84 v1(14.61,19.87) ; UA7.8 14.99,17.04
  TOP w0.254: RA217.2 13.97,12.06 v1(13.97,11.56) ; 14.99,17.04 14.81,16.86 v1(14.61,16.86) 14.47,17 CA33.1 12.51,17 12.49,16.97 CA39.1 11.1,16.97 v1(10.35,16.22)
  TOP w0.508: CA396.1 12.75,28.34 12.06,29.04 RA29.2
  IN1 w0.254: v1(14.61,19.87) 14.61,16.86 v1(14.61,16.86)
  IN2 w0.254: v1(9.16,19.45) 9.16,19.49 9.69,20.02 9.69,20.53 10.05,20.88 10.05,23.3 10.95,24.2 v1(12.07,24.2)
  BOTTOM w0.152: 15.25,19.33 15.28,19.33 15.57,19.05 JIO1.6
  BOTTOM w0.254: v1(13.97,11.56) 13.97,11.37 13.68,11.08 11.51,11.08 10.44,12.15 10.44,16.13 v1(10.35,16.22) ; 15.25,19.33 14.72,19.87 v1(14.61,19.87) 13.82,19.08 11.43,19.08 10.91,19.6 9.31,19.6 v1(9.16,19.45)
+3VALW: length 64.1
  TOP w0.254: v1(9.97,8.52) 11.24,8.52 v2(11.66,8.93) 11.66,9.75 12.96,11.06 16.62,11.06 16.68,11.12 16.7,11.12 17.09,11.5 RA213.2
  IN2 w0.254: v1(9.97,8.52) 9.72,8.77 9.72,15.14 9.87,15.29 9.87,16.92 9.91,16.96 9.91,19.48 10.07,19.65 10.07,20.17 10.66,20.76 10.96,20.76 v1(11.27,21.07) 11.67,21.47 11.67,22.61 12.64,23.57 12.64,24.71 11.12,26.23 11.12,36.26 10.35,37.03 10.35,52.46 9.21,53.6 8.58,53.6 v1(7.62,54.55)
  BOTTOM w0.254: v1(11.27,21.07) 11.63,20.7 14.13,20.7 14.26,20.58 14.99,20.58 15.52,20.05 JIO1.8
+3VS_AUDIO: length 17.2
  TOP w0.508: RA29.1 6.29,44.9 v3(6.83,45.44) 7.88,46.49
+3VS_AUDIO_R: length 1.5
  TOP w0.127: RA115.1 v2(6.48,50.04)
+5V_AVDD:
  vias: v3(21.78,12.71)
+5VALW:
  vias: v1(8.88,64.74) v1(8.88,64.15) v1(9.47,64.74) v1(9.47,64.15) v1(9.47,63.57) v1(10.06,64.74) v1(10.06,64.15) v1(10.06,63.57) v3(11.18,59.06)
+5VALWBP: length 2.4
  BOTTOM w0.254: 8.42,70.01 6.82,70.01 PC530.2 6.75,70.57 6.88,70.7 6.88,70.72 PR518.1
  vias: v3(10.16,69.98)
+5VS: length 52.1
  TOP w0.127: v3(4.77,54.68) 5.66,55.57 v1(6.57,55.57)
  TOP w0.356: QA1.2 6.62,56.46 RA122.1
  TOP w0.508: v1(6.57,55.57) QA1.2 ; RF10.1 v1(7.33,42.58)
  BOTTOM w0.152: JIO1.5 15.59,18.55 15.36,18.32 14.52,18.32 14.26,18.57
  BOTTOM w0.508: 14.26,18.57 11.22,18.57 10.7,19.09 10.14,19.09 9.88,18.84 8.42,18.84 6.93,20.34 6.93,39.06 6.42,39.57 6.42,42.17 6.82,42.58 v1(7.33,42.58) 7.62,42.87 7.62,52.97 6.86,53.74 6.86,55.28 v1(6.57,55.57)
+5VS_AUDIO:
  vias: v1(5.46,6.93) v1(5.46,6.29) v1(6.16,6.93) v1(6.16,6.29) v1(6.86,6.93) v1(6.86,6.29) v1(9.47,47.95) v1(9.47,47.31) v1(9.47,46.68) v1(16.39,24.33) v1(19.5,23.12) v1(21.26,9.62) v1(21.26,9.02) v1(21.9,10.13) v1(21.9,9.53) v1(22.48,10.13) v1(22.48,9.53) v3(11.05,44.01)
+5VS_AUDIO_R: length 1.3
  TOP w0.127: RA116.1 v2(11.69,50.04)
+5VS_FAN: length 2
  TOP w0.127: RF10.2 8.93,43.47 v2(8.64,43.76)
  TOP w0.508: RF10.2 v1(9.66,42.58)
AGND: length 20.7
  TOP w0.203: v1(20.32,21.02) 19.94,21.02 19.79,20.87 UA7.31 ; UA7.19 19.39,15.08 19.78,14.69 v1(20.11,14.69)
  TOP w0.356: CA51.1 22.46,22.32 CA24.2 ; v1(23.88,24.52) 23.75,24.64 CA309.1 22.81,24.29 CA29.2
  TOP w0.457: CA380.2 16.01,11.56 v1(15.12,11.56) ; CA394.2 24.32,16.01 24.77,15.56 v1(25.06,15.56)
  TOP w0.508: CA51.1 22.29,21.85 v1(21.91,21.85) ; CA19.2 v1(25.02,12.9) ; CA20.1 v1(25.02,14.8) ; CA82.1 20.97,24.59 v1(21.28,24.9) ; RA22.1 19.69,11.32 18.98,11.32 v1(18.8,11.5) ; RA10.1 v1(25.02,13.79)
  BOTTOM w0.356: 23.18,30.59 v1(23.75,30.59)
  BOTTOM w0.508: CA36.2 CA164.2 24.07,31.18 24.39,30.87 v1(24.39,30.61) ; v1(25.21,34.47) CA37.2 CA163.2 ; CA83.1 24.37,11.56 v1(25.04,11.56) ; v1(24.21,27.44) CA162.2 RA171.2 ; 18.8,15.5 RA23.1
  vias: v1(21.02,27.18) v1(25.85,23.95) v1(27.88,24.26) v1(28.03,26.93) v1(28.52,32.62) v1(28.52,30.84) v1(28.52,28.94) v1(32.52,26.1) v1(38.55,35.85) v1(38.6,24.24) v3(24.01,31.12) v3(24.39,21.22) v3(25.21,33.92)
GND: length 313.8
  TOP w0.203: UA2.11 v1(9.21,50.81)
  TOP w0.254: CA569.2 v1(8.47,20.22) ; v1(9.26,22.87) 9.1,22.7 CA568.2 ; DA9.1 v1(14.42,9.21) ; DA8.1 v1(17.85,9.21)
  TOP w0.305: EU1.3 v1(22.65,62.68)
  TOP w0.356: v1(13.97,16.52) 13.86,16.41 CA33.2 12.3,16.41 CA39.2 ; v1(7.56,55.25) CA999.2 RA511.2 ; CA147.2 v1(5.85,47.19) ; CA148.2 v1(19.28,24.16) ; CA399.2 CA390.2 21.56,10.7 v1(21.28,10.42) ; v1(5.46,53.99) 5.46,53.98 CA146.2 ; v1(5.46,54.58) 5.46,54.55 CA305.2 ; RV30.2 12.14,14.81 v1(12.7,15.37) ; v1(10.39,18.48) 10.39,18.54 10.29,18.64 CA555.1 ; CA44.2 16.64,7.69 v1(16.13,8.2) 15.62,7.69 CA49.2 ; v1(8.96,49.03) CA145.2 CA144.2 ; CA301.1 v1(5.85,47.82) ; v1(9.4,58.87) CA153.2 CA313.2 ; CA300.1 19.82,25.28 v1(19.88,25.22) ; CA302.1 v1(5.46,53.41)
  TOP w0.381: 19.88,44.52 v1(21.02,44.52)
  TOP w0.508: v1(19.97,23.53) 20.06,23.62 CA82.2 ; v1(10.39,18.48) 10.8,18.48 CA32.1 ; RA209.1 12.83,15.5 v1(12.7,15.37) ; CA396.2 v1(13.67,26.8) ; CA151.2 10.47,25.01 CA383.2 v1(9.78,25.03)
  GND1 w0.254: 25.71,57.05 JUSB1.11 ; JUSB1.11 27.27,58.95 ; JUSB1.11 28.83,58 ; JUSB1.11 28.83,57.05 ; JUSB1.11 25.71,58.95 ; JUSB1.11 25.71,58 ; JUSB1.11 27.27,57.05 ; 19.83,54.93 H1.1 ; H1.1 19.41,56.1 ; H1.1 22.17,54.93 ; H1.1 19.83,57.27 ; H1.1 22.59,56.1 ; H1.1 21,54.51 ; H1.1 21,57.69 ; H1.1 22.17,57.27 ; JUSB2.10 27.27,55.1 ; JUSB2.10 28.83,54.15 ; JUSB2.10 25.71,53.2 ; JUSB2.10 28.83,55.1 ; JUSB2.10 25.71,55.1 ; JUSB2.10 25.71,54.15 ; JUSB2.10 27.27,53.2 ; 33.31,73.7 JUSB1.12 ; JUSB1.12 34.77,74.65 ; JUSB1.12 36.23,74.65 ; JUSB1.12 36.23,73.7 ; JUSB1.12 33.31,74.65 ; 6.06,81.7 H21.1 ; H21.1 6.48,82.87 ; H21.1 6.48,80.53 ; H21.1 7.65,83.29 ; H21.1 8.82,82.87 ; H21.1 7.65,80.11 ; H21.1 8.82,80.53 ; H21.1 9.24,81.7 ; 21.21,2.8 H2.1 ; H2.1 21.63,1.63 ; H2.1 22.8,1.21 ; H2.1 24.39,2.8 ; H2.1 22.8,4.39 ; H2.1 21.63,3.97 ; H2.1 23.97,1.63 ; H2.1 23.97,3.97 ; 25.71,72.75 JUSB1.10 ; JUSB1.10 27.27,74.65 ; JUSB1.10 25.71,74.65 ; JUSB1.10 28.83,74.65 ; JUSB1.10 28.83,73.7 ; JUSB1.10 27.27,72.75 ; JUSB1.10 25.71,73.7 ; JUSB2.12 36.23,55.1 ; JUSB2.12 33.31,55.1 ; JUSB2.12 36.23,54.15 ; JUSB2.12 34.77,55.1 ; JUSB2.12 33.31,54.15 ; 24.94,49.8 JUSB2.4 ; JUSB2.4 26.42,49.8 ; JUSB2.4 26.25,50.37 ; JUSB2.4 25.68,49.06 ; JUSB2.4 25.68,50.54 ; JUSB2.4 25.11,49.23 ; JUSB2.4 26.25,49.23 ; JUSB2.4 25.11,50.37 ; JUSB1.4 26.42,69.35 ; JUSB1.4 25.11,69.92 ; JUSB1.4 25.11,68.78 ; JUSB1.4 25.68,68.61 ; JUSB1.4 26.25,69.92 ; JUSB1.4 24.94,69.35 ; JUSB1.4 25.68,70.09 ; JUSB1.4 26.25,68.78 ; 27.18,65.11 JUSB1.7 ; JUSB1.7 27.18,66.59 ; JUSB1.7 26.61,65.28 ; JUSB1.7 26.61,66.42 ; JUSB1.7 26.44,65.85 ; JUSB1.13 36.23,58 ; JUSB1.13 34.77,57.05 ; JUSB1.13 33.31,58 ; JUSB1.13 36.23,57.05 ; JUSB1.13 33.31,57.05 ; JUSB2.11 28.83,38.45 ; JUSB2.11 25.71,39.4 ; JUSB2.11 27.27,39.4 ; JUSB2.11 25.71,38.45 ; 26.44,46.3 JUSB2.7 ; JUSB2.7 26.61,45.73 ; JUSB2.7 27.18,45.56 ; JUSB2.7 27.18,47.04 ; JUSB2.7 26.61,46.87 ; 33.31,38.45 JUSB2.13 ; JUSB2.13 33.31,37.97 ; JUSB2.13 36.23,38.45
  GND2 w0.254: 25.71,55.1 JUSB2.10 ; JUSB2.10 27.27,55.1 ; JUSB2.10 27.27,53.2 ; JUSB2.10 28.83,55.1 ; JUSB2.10 25.71,53.2 ; JUSB2.10 25.71,54.15 ; JUSB2.10 28.83,54.15 ; 26.61,46.87 JUSB2.7 ; JUSB2.7 27.18,45.56 ; JUSB2.7 26.44,46.3 ; JUSB2.7 26.61,45.73 ; JUSB2.7 27.18,47.04 ; JUSB1.4 26.25,69.92 ; JUSB1.4 25.11,68.78 ; JUSB1.4 25.11,69.92 ; JUSB1.4 25.68,70.09 ; JUSB1.4 25.68,68.61 ; JUSB1.4 26.42,69.35 ; JUSB1.4 24.94,69.35 ; JUSB1.4 26.25,68.78 ; JUSB2.4 26.25,50.37 ; JUSB2.4 25.11,49.23 ; JUSB2.4 24.94,49.8 ; JUSB2.4 25.68,50.54 ; JUSB2.4 25.68,49.06 ; JUSB2.4 26.42,49.8 ; JUSB2.4 25.11,50.37 ; JUSB2.4 26.25,49.23 ; JUSB2.13 36.23,38.45 ; JUSB2.13 33.31,37.97 ; JUSB2.13 33.31,38.45 ; 21.63,3.97 H2.1 ; H2.1 21.21,2.8 ; H2.1 23.97,1.63 ; H2.1 21.63,1.63 ; H2.1 24.39,2.8 ; H2.1 22.8,1.21 ; H2.1 22.8,4.39 ; H2.1 23.97,3.97 ; JUSB2.12 36.23,55.1 ; JUSB2.12 33.31,54.15 ; JUSB2.12 33.31,55.1 ; JUSB2.12 36.23,54.15 ; JUSB2.12 34.77,55.1 ; 25.71,58.95 JUSB1.11 ; JUSB1.11 25.71,58 ; JUSB1.11 28.83,58 ; JUSB1.11 27.27,58.95 ; JUSB1.11 27.27,57.05 ; JUSB1.11 25.71,57.05 ; JUSB1.11 28.83,57.05 ; 25.71,73.7 JUSB1.10 ; JUSB1.10 27.27,72.75 ; JUSB1.10 25.71,74.65 ; JUSB1.10 25.71,72.75 ; JUSB1.10 28.83,74.65 ; JUSB1.10 27.27,74.65 ; JUSB1.10 28.83,73.7 ; 19.41,56.1 H1.1 ; H1.1 22.17,54.93 ; H1.1 22.59,56.1 ; H1.1 19.83,54.93 ; H1.1 21,54.51 ; H1.1 22.17,57.27 ; H1.1 21,57.69 ; H1.1 19.83,57.27 ; 6.06,81.7 H21.1 ; H21.1 6.48,82.87 ; H21.1 7.65,83.29 ; H21.1 9.24,81.7 ; H21.1 8.82,82.87 ; H21.1 7.65,80.11 ; H21.1 8.82,80.53 ; H21.1 6.48,80.53 ; JUSB1.12 36.23,74.65 ; JUSB1.12 34.77,74.65 ; JUSB1.12 33.31,74.65 ; JUSB1.12 36.23,73.7 ; JUSB1.12 33.31,73.7 ; JUSB2.11 27.27,39.4 ; JUSB2.11 25.71,38.45 ; JUSB2.11 28.83,38.45 ; JUSB2.11 25.71,39.4 ; 33.31,57.05 JUSB1.13 ; JUSB1.13 36.23,58 ; JUSB1.13 33.31,58 ; JUSB1.13 34.77,57.05 ; JUSB1.13 36.23,57.05 ; 26.61,66.42 JUSB1.7 ; JUSB1.7 26.44,65.85 ; JUSB1.7 27.18,66.59 ; JUSB1.7 27.18,65.11 ; JUSB1.7 26.61,65.28
  BOTTOM w0.254: JIO1.27 v1(15.04,29.55) ; v1(14.29,35.32) 14.29,35.31 14.35,35.25 14.55,35.25 14.86,34.93 15.31,34.93 15.43,35.05 JIO1.38 ; JIO1.35 15.18,33.55 JIO1.68 ; JIO1.29 15.18,30.55 JIO1.67 ; v1(14.86,26.68) 15.24,26.68 15.37,26.55 JIO1.21 ; v1(14.25,32.03) 14.23,32.03 14.23,32.05 JIO1.32
  BOTTOM w0.356: PC541.2 v1(17.34,72.4) ; PC545.2 PC546.2 v1(0.45,72.48) ; PC543.2 v1(17.34,71.13) ; PC542.2 v1(17.34,71.76) ; CU18.2 v1(6.91,60.23) ; PR513.1 9.2,71.24 v1(9.62,70.82) ; v1(17.29,63.56) CU8.1 CU9.2 ; PC544.2 v1(17.34,73.03) ; CU26.2 CU25.2 CU24.1 18,41.31 v1(17.91,41.22) ; v1(21.47,59.82) 21.05,60.24 CU10.2 CU4.2
  BOTTOM w0.508: DI2.1 20.35,47.19 v1(21.47,47.19) ; v1(19.56,16.47) 19.5,16.53 RA23.2 ; CA83.2 24.25,10.29 v1(25.02,10.29) ; CA18.2 21.34,20.71 20.25,19.61 v1(19.56,19.61) ; JFAN1.1 v1(7.16,39.82) ; v1(14.99,37.15) 15.19,36.95 JIO1.42 ; v1(2.43,59.9) PC536.2 ; DI1.1 20.92,66.49 v1(21.47,66.49) ; JIO2.5 10.32,6.77 v1(9.97,7.12) ; PC531.2 v1(15.05,81.09) ; PC535.2 v1(2.47,60.81) ; JSPK1.6 v1(20.01,6.74) ; v1(18.36,59.25) CU5.2 CU6.2 ; JFAN1.6 v1(5.86,46.22) ; v1(14.86,15.82) 15.03,15.65 JIO1.41 ; CU7.2 v1(16.35,57.52) ; UU1.2 v1(7.37,61.94) ; CU20.2 v1(20.83,39.57) ; CU19.2 v1(19.56,39.57) ; DA16.1 v1(21.4,38.26) ; JIO2.6 v1(2.63,6.77)
  vias: v1(0.43,81.6) v1(0.43,79.06) v1(0.43,76.52) v1(0.45,75) v1(0.43,73.98) v1(0.43,71.44) v1(0.43,68.9) v1(0.43,66.36) v1(0.43,63.82) v1(0.43,61.28) v1(0.43,11.08) v1(0.43,8.54) v1(0.45,7.25) v1(0.43,6) v1(0.6,58.74) v1(0.63,4.63) v1(0.76,3.48) v1(0.96,13.57) v1(1.18,9.84) v1(1.25,56.29) v1(1.29,12.3) v1(1.55,83.54) v1(1.72,76.17) v1(1.77,4.58) v1(1.91,53.84) v1(2.05,11.06) v1(2.05,9) v1(2.3,76.17) v1(2.51,12.88) v1(2.57,51.38) v1(2.63,7.52) v1(2.63,6.03) v1(2.63,5.14) v1(2.89,76.17) v1(3.23,48.93) v1(3.34,5.95) v1(3.34,4.78) v1(3.3,3.43) v1(3.47,76.17) v1(3.49,13.75) v1(3.56,11.44) v1(3.56,10.8) v1(3.56,10.22) v1(3.56,9.63) v1(3.56,9.05) v1(3.6,7.32) v1(3.81,67.72) v1(3.81,67.14) v1(3.81,66.55) v1(3.88,46.48) v1(4.09,83.54) v1(4.14,10.22) v1(4.14,9.63) v1(4.14,9.05) v1(4.23,23.8) v1(4.23,21.26) v1(4.23,18.72) v1(4.23,16.18) v1(4.4,67.72) v1(4.4,67.14) v1(4.38,43.99) v1(4.39,26.3) v1(4.58,69.82) v1(4.58,69.18) v1(4.7,41.47) v1(4.77,78.97) v1(4.94,78.26) v1(4.89,28.82) v1(5.02,38.95) v1(5.16,69.82) v1(5.16,69.18) v1(5.2,31.34) v1(5.27,36.42) v1(5.33,33.88) v1(5.38,78.7) v1(5.81,78.19) v1(5.84,3.43) v1(5.88,81.7) v1(6.39,78.14) v1(6.73,69.5) v1(6.73,68.92) v1(6.73,68.33) v1(6.73,67.75) v1(6.73,67.16) v1(6.73,66.58) v1(6.77,83.23) v1(6.77,80.17) v1(6.8,77.56) v1(6.8,76.93) v1(7.1,64.55) v1(7.38,77.83) v1(7.37,77.25) v1(8.38,3.43) v1(8.53,83.23) v1(8.53,80.17) v1(9.21,52.52) v1(9.42,81.7) v1(10.92,3.43) v1(11.8,83.55) v1(12.83,3.44) v1(13.53,48.52) v1(13.46,3.43) v1(13.55,57.77) v1(13.58,56.9) v1(13.58,56.27) v1(13.58,55.63) v1(13.58,55) v1(13.58,54.36) v1(13.58,51.34) v1(13.66,46.17) v1(13.66,44.39) v1(13.66,27.8) v1(13.78,33.6) v1(13.78,30.42) v1(14.1,63.82) v1(14.35,67.19) v1(14.42,48.08) v1(14.42,46.3) v1(14.74,61.86) v1(14.74,61.22) v1(14.99,67.19) v1(14.99,56.97) v1(14.99,54.93) v1(14.99,52.84) v1(14.99,44.65) v1(14.95,42.77) v1(15.28,83.55) v1(15.31,64.78) v1(15.43,37.66) v1(15.82,49.41) v1(16,3.43) v1(16.44,28.52) v1(16.44,26.55) v1(16.41,19.61) v1(16.41,18.04) v1(16.41,16.47) v1(16.52,81.65) v1(16.52,79.11) v1(16.45,36.58) v1(16.45,33.53) v1(16.48,30.71) v1(16.45,25.05) v1(17.42,74.94) v1(17.74,76.88) v1(17.93,70.4) v1(17.93,69.81) v1(17.93,69.15) v1(17.93,68.57) v1(18.48,44.43) v1(18.54,3.43) v1(19.12,10.42) v1(19.23,56.1) v1(19.31,27.31) v1(19.37,66.68) v1(19.37,64.97) v1(19.54,31.98) v1(19.54,29.94) v1(19.56,18.04) v1(19.68,74.91) v1(19.7,72.9) v1(19.78,70.59) v1(19.93,64.27) v1(19.93,1.3) v1(20.01,27.25) v1(20.12,57.63) v1(20.12,54.57) v1(20.28,76.87) v1(21.03,2.8) v1(21.43,74) v1(21.4,71.81) v1(21.47,69.09) v1(21.47,67.25) v1(21.47,50.23) v1(21.48,42.88) v1(21.61,64.4) v1(21.94,75.75) v1(21.88,57.63) v1(21.88,54.57) v1(21.92,4.33) v1(21.92,1.27) v1(22.04,48.7) v1(22.72,46.79) v1(22.82,76.87) v1(22.77,56.1) v1(22.8,0.58) v1(23,72.62) v1(23,70.29) v1(23.03,67.29) v1(23.03,65.06) v1(23.03,50.88) v1(23.03,48.67) v1(23.08,61.02) v1(23.68,4.33) v1(23.68,1.27) v1(24.04,73.79) v1(24.04,71.48) v1(24.04,64.29) v1(24.02,52) v1(24.04,48.04) v1(24.04,45.68) v1(24.1,75.01) v1(24.07,68.92) v1(24.07,66.45) v1(24.1,53.96) v1(24.07,50.04) v1(24.17,57.97) v1(24.57,2.8) v1(24.86,0.44) v1(25.04,38.36) v1(25.36,76.87) v1(25.37,56.65) v1(25.37,8) v1(25.37,5.46) v1(25.62,55.38) v1(25.72,75.42) v1(27.04,59.95) v1(27.12,52.03) v1(27.09,40.57) v1(27.27,71.48) v1(27.9,76.87) v1(29.12,39.05) v1(29.23,75.52) v1(29.2,56.65) v1(29.23,55.43) v1(29.2,53.48) v1(29.28,73.03) v1(30.03,58.67) v1(30.44,76.87) v1(30.37,37.95) v1(30.5,57.41) v1(31.06,55.05) v1(31.49,75.52) v1(31.64,39.12) v1(31.74,53.48) v1(31.82,73.03) v1(32.1,56.09) v1(32.33,57.36) v1(32.57,58.67) v1(32.71,54.51) v1(32.83,37.9) v1(32.98,76.87) v1(33.65,56.01) v1(35.02,75.44) v1(35.2,56.04) v1(35.52,76.87) v1(36.31,39.12) v1(36.74,57.16) v1(36.72,54.79) v1(36.82,53.48) v1(36.9,73.03) v1(37.64,75.46) v1(37.64,58.43) v1(37.64,55.89) v1(37.6,37.92) v3(4.83,51.95) v3(8.13,5.4) v3(16.51,51.06)
+LINE1_VREFO_L: length 4.2
  TOP w0.203: UA7.24 21.01,17.44 21.27,17.19 21.72,17.19 22.13,16.78 v1(22.13,16.73)
  BOTTOM w0.305: DA18.1 23.63,16.45 23.24,16.07 v2(22.8,16.07) 22.79,16.07 v1(22.13,16.73)
+MIC2-VREFO: length 25
  TOP w0.203: UA7.23 20.95,17.04 21.26,16.73 v1(21.53,16.73)
  BOTTOM w0.305: RA169.1 RA172.1 26.89,32.59 27.44,32.05 27.44,29.72 v2(26.13,28.42) 24.9,27.18 24.9,17.72 24.51,17.34 24.51,16.26 23.64,15.39 23.51,15.39 23.5,15.37 22.42,15.37 21.53,16.26 v1(21.53,16.73)
+RTC_CELL: length 20.2
  TOP w0.254: v1(13.15,10.55) 13.28,10.67 16.96,10.67 v2(17.31,11.02) 17.91,11.63 RA227.2
  BOTTOM w0.254: v1(13.15,10.55) 13,10.7 11.35,10.7 10.06,11.99 10.06,15.83 9.87,16.02 9.87,16.47 10.1,16.71 13.01,16.71 13.68,16.03 14.17,16.03 14.46,16.33 15.37,16.33 15.59,16.55 JIO1.1
+USB3_VCC:
  vias: v1(16.01,63.38) v1(16.01,62.74) v1(16.64,63.38) v1(16.64,62.74) v1(19.37,43) v1(19.37,42.36) v1(20.01,43) v1(20.01,42.36) v3(10.23,61.86)
AUD_HP1_JACK_L: length 15
  IN2 w0.305: v1(21.29,23.48) 21.63,23.48 23.31,25.15 24.2,25.15 24.96,24.39 24.96,18.88 23.42,17.34 21.97,17.34 v1(21.66,17.66)
  BOTTOM w0.305: v1(21.29,23.48) 21.45,23.31 RA133.1
AUD_HP1_JACK_L1: length 4
  BOTTOM w0.305: RA200.2 23.44,21.28 v2(22.86,21.85) 22.37,22.35 RA133.2 22.37,23.57 LA28.1
AUD_HP1_JACK_R: length 8.3
  IN2 w0.305: v1(23.89,23.88) 23.94,23.83 23.94,18.84 23.14,18.04 v1(22.17,18.04)
  BOTTOM w0.305: RA134.1 23.89,22.93 v1(23.89,23.88)
AUD_HP1_JACK_R1: length 4.1
  BOTTOM w0.305: LA30.1 23.16,23.65 23.1,23.6 RA134.2 23.1,22.69 24.12,21.67 v2(24.12,21.15) 24.12,20.16 RA33.2
AUD_PC_BEEP: length 2.6
  TOP w0.102: UA7.11 16.19,15.3 15.18,14.29 CA14.2
AUD_PC_BEEP_C: length 3.6
  TOP w0.102: RA9.1 9.1,13.39 v2(8.89,13.6) 8.32,14.17 DA19.1
AUD_SENSE_A:
  vias: v2(15.69,14.17)
AUD_VREF:
  vias: v2(21.72,16.2)
B+: length 0.8
  BOTTOM w0.127: v3(6.04,59.72) 5.69,59.72 v1(5.4,60.01)
  vias: v1(4.77,61.18) v1(4.77,60.6) v1(4.77,60.01) v1(5.4,62.35) v1(5.4,61.77) v1(5.4,61.18) v1(5.4,60.6) v1(7.78,10.36) v1(7.78,9.78) v1(8.36,10.36) v1(8.36,9.78) v1(8.92,11.53) v1(8.92,10.95) v1(8.94,10.36) v1(8.94,9.78)
BEEP: length 22
  TOP w0.102: v1(10.59,9.02) 10.16,9.45 10.16,11.18 v2(9.81,11.53) 7.32,14.02 DA19.3
  IN1 w0.135: v1(10.59,9.02) 9.99,9.63 9.99,15.62 9.38,16.22 v1(9.38,16.26)
  BOTTOM w0.102: v1(9.38,16.26) 9.38,16.42 10.01,17.05 14.19,17.05 14.42,17.28 14.95,17.28 15.18,17.05 JIO1.2
CPVEE: length 1.8
  TOP w0.203: v1(21.4,18.71) 21.33,18.64 UA7.27
  BOTTOM w0.305: CA18.1 22,19.31 v1(21.4,18.71)
DMIC_CLK: length 5.9
  TOP w0.102: L7.2 10.58,21.16 11.1,20.64 13.14,20.64 v2(13.22,20.55) 13.88,19.89 13.88,19.7 14.37,19.21 14.7,19.21 14.87,19.04 UA7.3
DMIC_CLK_CODEC: length 15.3
  TOP w0.102: CA569.1 8.53,21.48 v1(9.08,21.48) 9.43,21.48 L7.1
  BOTTOM w0.102: JIO1.26 10.98,29.05 8.34,26.42 8.34,22.03 8.89,21.48 v1(9.08,21.48)
DMIC_DATA: length 6.5
  TOP w0.102: UA7.2 14.46,19.44 14.19,19.72 14.19,20.05 14.29,20.15 14.29,20.33 13.38,21.24 12.2,21.24 v2(12.13,21.31) 11.29,22.15 RA222.2
DMIC_DATA_CODEC: length 13.3
  TOP w0.102: RA222.1 9.62,22.12 v1(9.03,22.12) CA568.1
  BOTTOM w0.102: JIO1.25 11.18,28.55 8.83,26.2 8.83,22.32 v1(9.03,22.12)
EC_MUTE#: length 22
  TOP w0.102: UA7.40 16.19,20.84 16.07,20.96 14.7,20.96 v2(14.37,21.29) 13.9,21.29 RA206.2 12.84,22.4 11.93,23.31 10.99,23.31 10.99,23.31 9.43,23.31 9.08,23.65 8.32,23.65 8.04,23.37 8.04,19.35 v1(9.16,18.23)
  BOTTOM w0.102: v1(9.16,18.23) 9.34,18.05 JIO1.4
EN_5V: length 63
  IN1 w0.135: v1(4.59,72.28) 4.72,72.28 8.49,68.51 10.79,68.51 11.67,67.63 11.67,67.1 11.52,66.96 10.51,66.96 8.27,64.72 8.27,58.65 10.88,56.03 10.88,26.02 11.27,25.64 11.27,23.71 12.21,22.77 v1(12.21,22.46)
  BOTTOM w0.102: JIO1.12 15.49,22.05 15.28,22.26 13.98,22.26 13.78,22.46 12.23,22.46 12.23,22.46 v1(12.21,22.46)
  BOTTOM w0.254: v1(4.59,72.28) 4.63,72.32 5.25,72.32 5.59,72.66 PU502.15
FB_5VB: length 3.1
  BOTTOM w0.254: PU502.13 6.59,72.48 6.87,72.19 PR518.2 6.11,71.64 PR517.2 5.87,71.42 5.36,71.42 PR519.1
HDA_BIT_CLK_R: length 23.3
  TOP w0.102: UA7.5 14.92,18.24 14.78,18.38 13.98,18.38 12.92,19.44 10.99,19.44 10.63,19.79 CA555.2 9.97,19.79 v1(9.08,20.68)
  BOTTOM w0.102: JIO1.28 14.62,30.05 14.1,29.53 10.78,29.53 7.86,26.62 7.86,21.6 8.78,20.68 v1(9.08,20.68)
HDA_SDIN0: length 14
  TOP w0.102: RA17.1 10.29,17.79 v2(9.78,18.29) 9.66,18.42 9.66,19.52 v1(9.08,20.1)
  BOTTOM w0.102: v1(9.08,20.1) 9.23,20.1 9.98,20.84 9.98,23.26 10.35,23.63 11.69,23.63 12,23.32 15.3,23.32 15.57,23.05 JIO1.14
HDA_SDIN0_R: length 3
  TOP w0.102: UA7.7 14.33,17.44 v2(14.29,17.41) 13.66,17.41 13.28,17.79 RA17.2
HDA_SDOUT_R: length 14.4
  TOP w0.102: v1(10.94,20.12) 11.25,19.81 13.07,19.81 14.11,18.77 v2(14.29,18.77) 14.83,18.77 14.96,18.64 UA7.4
  BOTTOM w0.102: JIO1.13 15.62,22.55 15.08,23.09 11.84,23.09 11.56,23.37 10.42,23.37 10.21,23.17 10.21,20.85 v1(10.94,20.12)
HDA_SYNC_R: length 21.5
  TOP w0.102: v1(9.38,15.49) 9.39,15.5 v2(11.05,15.5) 12.2,15.5 12.7,16.01 14.03,16.01 14.48,16.45 14.86,16.45 15.05,16.64 UA7.9
  IN1 w0.135: v1(9.78,23.82) 9.78,19.82 9.66,19.69 9.66,17.21 8.96,16.52 8.96,15.91 v1(9.38,15.49)
  BOTTOM w0.102: v1(9.78,23.82) 9.85,23.88 11.81,23.88 12.15,23.55 15.75,23.55 JIO1.15
HPOUT_L: length 21.1
  IN1 w0.305: v1(22.74,33.93) 24.82,36.01 28.68,36.01 29.9,34.79 JHP1.2 ; v1(21.62,33.05) 21.62,30.14 22.43,29.33 v1(22.43,27.18)
  BOTTOM w0.127: v2(23.37,27.88) 23.12,27.88 22.43,27.2 v1(22.43,27.18)
  BOTTOM w0.305: LA28.2 22.43,24.64 RA170.1 CA161.1 v1(22.43,27.18) ; v1(22.74,33.93) DA15.2 v1(21.62,33.05)
HPOUT_R: length 27.7
  IN1 w0.305: v1(22.79,32) 22.79,32.98 22.17,33.6 22.17,34.74 24.13,36.71 32.77,36.71 34.69,34.79 JHP1.3 ; v1(23.18,27.18) 23.18,29.58 22.74,30.03 v1(22.74,31.15)
  BOTTOM w0.305: v1(23.18,27.18) 23.18,27.06 23.3,26.94 CA162.1 RA171.1 23.3,24.61 23.18,24.5 ; v1(22.74,31.15) 21.78,31.15 21.62,31.31 DA15.3 v1(22.79,32)
JACK_PLUG: length 40.2
  TOP w0.102: RA207.1 13.39,12.07 v1(13.39,11.56) ; v1(23.69,29.34) 23.82,29.34 v2(24.26,28.9) 27.37,25.79 JHP1.5
  IN2 w0.135: v1(13.39,11.56) 13.39,12.76 16.2,15.56 20.2,15.56 20.77,16.14 20.77,17.47 22.04,18.74 22.99,18.74 23.24,18.99 23.24,21.98 22.67,22.55 21.4,22.55 20.83,23.12 20.83,23.69 23.69,26.55 23.69,27.5 22.23,28.96 v1(21.62,28.96)
  BOTTOM w0.102: v1(21.62,28.96) DA14.3 22.41,28.06 v1(23.69,29.34)
JACK_PLUG_DET: length 17.6
  TOP w0.102: v1(23.71,30) 23.18,29.47 23.18,29.15 v2(25.69,26.64) 27.44,24.9 32.26,24.9 33.15,25.79 JHP1.6
  BOTTOM w0.102: v1(23.71,30) RA168.1 23.17,29.99 DA14.2
LDO1_CAP:
  vias: v2(21.72,14.87)
LDO2_CAP: length 2.7
  TOP w0.203: UA7.32 19.39,21 20.07,21.68 v2(20.18,21.68)
  TOP w0.381: v2(20.18,21.68) 20.67,22.17 21.21,22.17 CA51.2
LDO3_CAP: length 3.3
  TOP w0.203: UA7.6 14.23,17.84 14.21,17.87
  TOP w0.381: 14.21,17.87 13.77,17.87 12.83,18.8 12.51,18.8
